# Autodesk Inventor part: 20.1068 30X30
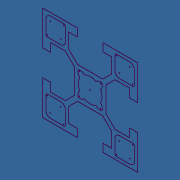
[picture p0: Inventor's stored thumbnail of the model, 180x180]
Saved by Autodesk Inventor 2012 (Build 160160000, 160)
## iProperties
Created: 2005-12
Part Number: 20.1068 30X30
Document SubType Name: Modeling
Designer: Administrator
Material: Aluminum-6061
Description: PROFILE 30X30
Stock Number: 20.1068 PROFILE 30X30
Density: 2.71 g/cm^3
FINISH: CLEAR ANODIZED
Author: Administrator
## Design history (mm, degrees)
sketch "Sketch1"
  geometry: L1 (13.5, -7.8)-(9.3, -7.8) reference; L2 (14, -12.5)-(14, -8.3) reference; L3 (8.3, -14)-(12.5, -14) reference; L4 (7.8, -9.3)-(7.8, -13.5) reference; L5 (-9.3, -7.8)-(-13.5, -7.8) reference; L6 (-7.8, -13.5)-(-7.8, -9.3) reference; L7 (-12.5, -14)-(-8.3, -14) reference; L8 (-14, -8.3)-(-14, -12.5) reference; L9 (3.286, 3.879)-(2.243, 3.657) reference; L10 (3.657, 2.243)-(3.879, 3.286) reference; L11 (3.263, 1.849)-(3.657, 2.243) reference; L12 (3.657, -2.243)-(3.263, -1.849) reference; L13 (3.879, -3.286)-(3.657, -2.243) reference; L14 (2.243, -3.657)-(3.286, -3.879) reference; L15 (1.849, -3.263)-(2.243, -3.657) reference; L16 (-2.243, -3.657)-(-1.849, -3.263) reference; L17 (-3.286, -3.879)-(-2.243, -3.657) reference; L18 (-3.657, -2.243)-(-3.879, -3.286) reference; L19 (-3.263, -1.849)-(-3.657, -2.243) reference; L20 (-3.657, 2.243)-(-3.263, 1.849) reference; L21 (-3.879, 3.286)-(-3.657, 2.243) reference; L22 (-2.243, 3.657)-(-3.286, 3.879) reference; L23 (-1.849, 3.263)-(-2.243, 3.657) reference; L24 (2.243, 3.657)-(1.849, 3.263) reference; L25 (9.3, 7.8)-(13.5, 7.8) reference; L26 (7.8, 13.5)-(7.8, 9.3) reference; L27 (12.5, 14)-(8.3, 14) reference; L28 (14, 8.3)-(14, 12.5) reference; L29 (-8.3, 14)-(-12.5, 14) reference; L30 (-7.8, 9.3)-(-7.8, 13.5) reference; L31 (-13.5, 7.8)-(-9.3, 7.8) reference; L32 (-14, 12.5)-(-14, 8.3) reference; L33 (12.5, 4.1)-(12.5, 6.8) reference; L34 (15, 4.1)-(12.5, 4.1) reference; L35 (15, 15)-(15, 4.1) reference; L36 (4.1, 15)-(15, 15) reference; L37 (4.1, 12.5)-(4.1, 15) reference; L38 (6.8, 12.5)-(4.1, 12.5) reference; L39 (6.8, 7.861)-(6.8, 12.5) reference; L40 (3.971, 5.032)-(6.8, 7.861) reference; L41 (-3.971, 5.032)-(3.971, 5.032) reference; L42 (-6.8, 7.861)-(-3.971, 5.032) reference; L43 (-6.8, 12.5)-(-6.8, 7.861) reference; L44 (-4.1, 12.5)-(-6.8, 12.5) reference; L45 (-4.1, 15)-(-4.1, 12.5) reference; L46 (-15, 15)-(-4.1, 15) reference; L47 (-15, 4.1)-(-15, 15) reference; L48 (-12.5, 4.1)-(-15, 4.1) reference; L49 (-12.5, 6.8)-(-12.5, 4.1) reference; L50 (-7.861, 6.8)-(-12.5, 6.8) reference; L51 (-5.032, 3.971)-(-7.861, 6.8) reference; L52 (-5.032, -3.971)-(-5.032, 3.971) reference; L53 (-7.861, -6.8)-(-5.032, -3.971) reference; L54 (-12.5, -6.8)-(-7.861, -6.8) reference; L55 (-12.5, -4.1)-(-12.5, -6.8) reference; L56 (-15, -4.1)-(-12.5, -4.1) reference; L57 (-15, -15)-(-15, -4.1) reference; L58 (-4.1, -15)-(-15, -15) reference; L59 (-4.1, -12.5)-(-4.1, -15) reference; L60 (-6.8, -12.5)-(-4.1, -12.5) reference; L61 (-6.8, -7.861)-(-6.8, -12.5) reference; L62 (-3.971, -5.032)-(-6.8, -7.861) reference; L63 (3.971, -5.032)-(-3.971, -5.032) reference; L64 (6.8, -7.861)-(3.971, -5.032) reference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; A1 r 1.5 centre (9.3, -9.3) between (9.3, -7.8) and (7.8, -9.3) reference; A2 r 0.5 centre (13.5, -8.3) between (14, -8.3) and (13.5, -7.8) reference; A3 r 1.5 centre (12.5, -12.5) between (12.5, -14) and (14, -12.5) reference; A4 r 0.5 centre (8.3, -13.5) between (7.8, -13.5) and (8.3, -14) reference; A5 r 0.5 centre (-13.5, -8.3) between (-13.5, -7.8) and (-14, -8.3) reference; A6 r 1.5 centre (-9.3, -9.3) between (-7.8, -9.3) and (-9.3, -7.8) reference; A7 r 0.5 centre (-8.3, -13.5) between (-8.3, -14) and (-7.8, -13.5) reference; A8 r 1.5 centre (-12.5, -12.5) between (-14, -12.5) and (-12.5, -14) reference; A9 r 0.5 centre (3.39, 3.39) between (3.879, 3.286) and (3.286, 3.879) reference; A10 r 0.5 centre (3.39, -3.39) between (3.286, -3.879) and (3.879, -3.286) reference; A11 r 3.75 centre (0, 0) between (-1.849, -3.263) and (1.66, -3.362) reference; A12 r 0.5 centre (-3.39, -3.39) between (-3.879, -3.286) and (-3.286, -3.879) reference; A13 r 3.75 centre (0, 0) between (-3.362, 1.66) and (-3.263, -1.849) reference; A14 r 0.5 centre (-3.39, 3.39) between (-3.286, 3.879) and (-3.879, 3.286) reference; A15 r 0.5 centre (13.5, 8.3) between (13.5, 7.8) and (14, 8.3) reference; A16 r 1.5 centre (9.3, 9.3) between (7.8, 9.3) and (9.3, 7.8) reference; A17 r 0.5 centre (8.3, 13.5) between (8.3, 14) and (7.8, 13.5) reference; A18 r 1.5 centre (12.5, 12.5) between (14, 12.5) and (12.5, 14) reference; A19 r 1.5 centre (-12.5, 12.5) between (-12.5, 14) and (-14, 12.5) reference; A20 r 0.5 centre (-8.3, 13.5) between (-7.8, 13.5) and (-8.3, 14) reference; A21 r 1.5 centre (-9.3, 9.3) between (-9.3, 7.8) and (-7.8, 9.3) reference; A22 r 0.5 centre (-13.5, 8.3) between (-14, 8.3) and (-13.5, 7.8) reference; A23 r 3.75 centre (0, 0) between (-3.263, 1.849) and (-3.362, 1.66) reference; A24 r 3.75 centre (0, 0) between (3.362, 1.66) and (3.263, 1.849) reference; A25 r 3.75 centre (0, 0) between (1.849, 3.263) and (-1.849, 3.263) reference; A26 r 3.75 centre (0, 0) between (1.66, -3.362) and (1.849, -3.263) reference; A27 r 3.75 centre (0, 0) between (3.263, -1.849) and (3.362, 1.66) reference; 1 further point
  constraints: 152 end point, 54 point on circle, 27 centre point, 26 horizontal, 26 vertical, 179 other
